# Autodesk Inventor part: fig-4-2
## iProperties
Shininess: 64.0
Length Units: 11272
Angle Units: 11279
Time Units: 11290
Mass Units: 11283
Length Display Precision: 3
Angle Display Precision: 2
Compacted: True
Part Number: fig-4-2
Document SubType Name: Modeling
Created: 2003-01
Designer: Owner
Density: 1 g/cm^3
Density: 0.0
Volumn: 0.0
Area: 0.0
PropertySet Name: Model Information
Control State: 0
Master: False
Checked Out: False
Author: Owner
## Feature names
1. ExtrusionBlind1
